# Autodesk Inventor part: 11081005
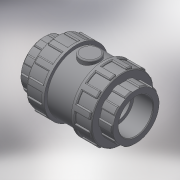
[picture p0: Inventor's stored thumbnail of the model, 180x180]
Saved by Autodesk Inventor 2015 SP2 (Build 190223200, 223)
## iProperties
Created: 2017-11
Part Number: 11081005
Material: Generic
Description: PLASSON CHECK VALVE THR 1/2" PTFE COATED SPRING + EPDM O-RING
Document SubType Name: Modeling
Designer: KIM
Density: 1 g/cm^3
Appearance: Default
Author: KIM
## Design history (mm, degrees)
derived "110810 - 110610 110910 - 110010.ipt"
feature "Solid1::110810 - 110610 110910 - 110010.ipt"
tag "TaggingFeature1"
body "Solid1"
other parameters: "d0" = 75, "d1" = 18.631, "d2" = 45, "d3" = 16, "d4" = 14.9048, "d5" = 11.2, "d7" = 26.0834, "d8" = 40.5, "d13" = 0.55893, "d23" = 16, "d24" = 43.2, "d25" = 0.37262, "d26" = 0.55893, "d27" = 6.75, "d28" = 3.375, "d29" = 12, "d30" = 0, "d35" = 0.55893, "d39" = 22.5, "d45" = 360 deg, "d47" = 0.37262, "d50" = 22.5, "d51" = 13.5, "d53" = 0, "d54" = 0.9, "d55" = 3.7262, "d56" = 1.8631, "d58" = 0, "d59" = 0.55893, "d61" = 360 deg, "G_" = 18.631, "l_" = 16, "H_" = 75, "K_" = 45
